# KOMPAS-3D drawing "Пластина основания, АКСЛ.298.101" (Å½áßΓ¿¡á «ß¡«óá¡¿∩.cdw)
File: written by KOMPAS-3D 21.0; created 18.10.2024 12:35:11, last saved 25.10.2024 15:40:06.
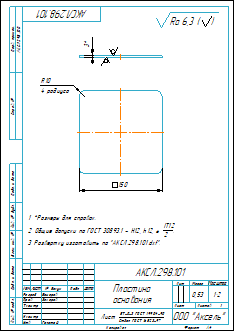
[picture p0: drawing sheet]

Sheet 1: A4, portrait

Document properties: Автор: Алексей Бочаров; Знак неуказанной шероховатости: 4; Параметр неуказанной шероховатости: Ra 6,3; Масса: 0.528257

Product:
- Part/product: Пластина основания  | designation АКСЛ.298.101
    Масса: 0.528257
    Форматы листов документа: A4

Title block, sheet 1: Наименование: Пластина / основания; designation: АКСЛ.298.101; Материал: Лист  БТ-0-3 ГОСТ 19904-90 Ст3сп ГОСТ 16523-97; Масса: 0,53; Количество листов документа: 1; organisation: ООО "Аксель"; Форматы листов документа: A4; stored path: C:\Users\Алексей Бочаров\YandexDisk\Соединения бруса\Соединения бруса\ОСНОВАНИЕ\Пластина основания.cdw; Разработал: Бочаров; Проверил: Захаров; Утвердил: Гелетей

Views: Вид 1, Спереди, Проекционный вид 2
Referenced files in C:\Users\Алексей Бочаров\YandexDisk\Соединения бруса\Соединения бруса\ОСНОВАНИЕ\: Пластина основания.m3d
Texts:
  Ra 6,3
  Ra 6,3 ( )
  АКСЛ.298.100
  АКСЛ.298.101 Пластина основания
Dimensions and other numbers on the sheet: 3; 150; 10; 4 радиуса; 1:2; 1; 0,53

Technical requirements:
  *Размеры для справок.
  Общие допуски по ГОСТ 30893.1 - H12, h12,    IT12 2 .
  Развертку изготовить по "АКСЛ.298.101.dxf".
